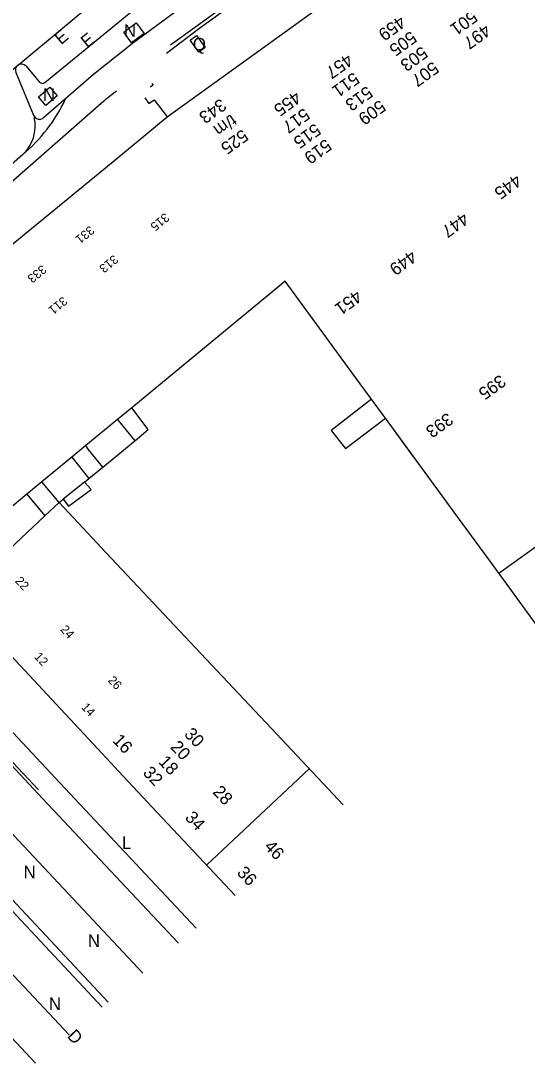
# Model space of a CAD drawing. Extents: x 81617 to 82144, y 454649 to 455150.
# Drawn here: x 81909.6 to 81949.9, y 454809.9 to 454892.9 of the extents above; entities that cross this region are included whole.
import ezdxf

# ---------------------------------------------------------------- set-up
doc = ezdxf.new("R2010")
doc.units = 0
doc.layers.add('B-WE-OG-TOPOGRAFIE-G', color=7, linetype='Continuous')
doc.layers.add('B-WE-VW-MARKERING-G', color=7, linetype='Continuous')

msp = doc.modelspace()

# ---------------------------------------------------------------- linework, layer by layer
at = {"layer": 'B-WE-OG-TOPOGRAFIE-G'}
for p, q in [((81950.918, 454911.808), (81923.86, 454892.262)), ((81944.326, 454907.373), (81921.528, 454890.929)), ((81923.86, 454892.262), (81921.201, 454890.255)), ((81909.22, 454888.733), (81910.638, 454885.336)), ((81917.237, 454887.263), (81916.786, 454886.922)), ((81916.221, 454886.463), (81896.497, 454869.183)), ((81919.488, 454886.723), (81919.813, 454886.277)), ((81919.813, 454886.277), (81920.236, 454886.581)), ((81920.236, 454886.581), (81921.268, 454885.205)), ((81937.511, 454862.758), (81934.312, 454860.275)), ((81937.511, 454862.758), (81934.312, 454860.275)), ((81937.511, 454862.758), (81934.312, 454860.275)), ((81918.444, 454862.075), (81917.306, 454861.136)), ((81917.306, 454861.136), (81914.799, 454859.068)), ((81917.306, 454861.136), (81918.676, 454859.457)), ((81935.433, 454858.848), (81938.614, 454861.25)), ((81935.433, 454858.848), (81938.614, 454861.25)), ((81935.433, 454858.848), (81938.614, 454861.25)), ((81934.312, 454860.275), (81935.433, 454858.848)), ((81934.312, 454860.275), (81935.433, 454858.848)), ((81934.312, 454860.275), (81935.433, 454858.848)), ((81914.799, 454859.068), (81913.685, 454858.149)), ((81916.149, 454857.354), (81918.676, 454859.457)), ((81913.685, 454858.149), (81911.291, 454856.174)), ((81913.685, 454858.149), (81915.028, 454856.444)), ((81915.028, 454856.444), (81916.149, 454857.354)), ((81914.671, 454856.155), (81915.028, 454856.444)), ((81911.291, 454856.174), (81910.108, 454855.198)), ((81912.663, 454854.533), (81911.291, 454856.174)), ((81914.671, 454856.155), (81912.984, 454854.792)), ((81910.108, 454855.198), (81905.083, 454851.053)), ((81910.108, 454855.198), (81911.539, 454853.481)), ((81912.663, 454854.533), (81912.984, 454854.792)), ((81947.643, 454848.911), (81956.042, 454855)), ((81911.539, 454853.481), (81912.663, 454854.533)), ((81906.763, 454849.012), (81911.539, 454853.481)), ((81924.393, 454825.698), (81932.567, 454833.351)), ((81906.018, 454826.058), (81916.564, 454814.799)), ((81916.1, 454814.409), (81905.567, 454825.643))]:
    msp.add_line(p, q, dxfattribs=at)
for points in [[(81917.092, 454881.782), (81921.268, 454885.205), (81949.801, 454905.786)], [(81919.999, 454898.128), (81906.308, 454886.765), (81902.426, 454883.614), (81900.642, 454882.153)], [(81911.534, 454887.943), (81921.736, 454896.324)], [(81911.427, 454885.151), (81915.4, 454888.603), (81918.504, 454891.084), (81923.337, 454894.66)], [(81919.423, 454891.854), (81918.433, 454891.108), (81917.801, 454891.947), (81918.791, 454892.693), (81919.423, 454891.854)], [(81923.597, 454891.675), (81924.274, 454890.72), (81923.769, 454890.369), (81923.093, 454891.323), (81923.597, 454891.675)], [(81910.021, 454889.265), (81911.115, 454887.981)], [(81920.043, 454887.868), (81920.135, 454887.739), (81919.902, 454887.577)], [(81911.027, 454886.805), (81911.932, 454887.574), (81912.512, 454886.885), (81911.605, 454886.11), (81911.027, 454886.805)], [(81891.095, 454859.963), (81890.844, 454860.269), (81917.092, 454881.782)], [(81951.285, 454843.934), (81946.864, 454849.976), (81944.717, 454852.907), (81938.617, 454861.252), (81938.467, 454861.458), (81936.615, 454863.983), (81930.646, 454872.141), (81929.047, 454870.822)], [(81929.231, 454870.974), (81918.444, 454862.075)], [(81929.231, 454870.974), (81929.047, 454870.822)], [(81940.891, 454858.141), (81938.617, 454861.252), (81938.467, 454861.458), (81936.615, 454863.983), (81935.739, 454865.18)], [(81940.891, 454858.141), (81938.617, 454861.252), (81938.467, 454861.458), (81936.615, 454863.983), (81935.739, 454865.18)], [(81918.676, 454859.457), (81919.752, 454860.352), (81918.444, 454862.075)], [(81916.149, 454857.354), (81914.976, 454858.774), (81914.799, 454859.068)], [(81912.984, 454854.792), (81913.418, 454854.239), (81915.212, 454855.566), (81914.671, 454856.155)], [(81912.663, 454854.533), (81916.411, 454850.545), (81923.933, 454842.539)], [(81912.733, 454832.236), (81908.633, 454836.613), (81900.431, 454845.439), (81899.742, 454846.157), (81896.321, 454849.804), (81892.737, 454853.657), (81891.454, 454852.381)], [(81891.454, 454852.381), (81907.325, 454835.276), (81911.365, 454830.977)], [(81915.707, 454834.971), (81906.614, 454844.709), (81904.504, 454846.96), (81905.266, 454847.61)], [(81923.933, 454842.539), (81928.656, 454837.512), (81929.128, 454837.011), (81935.259, 454830.486)], [(81926.662, 454823.272), (81920.473, 454829.89), (81917.383, 454833.177), (81917.088, 454833.492), (81915.707, 454834.971)], [(81923.564, 454820.673), (81912.733, 454832.236)], [(81911.365, 454830.977), (81922.158, 454819.493)], [(81919.317, 454817.11), (81908.659, 454828.488)], [(81903.018, 454823.298), (81913.463, 454812.197)], [(81910.78, 454809.946), (81900.471, 454820.954)]]:
    msp.add_lwpolyline(points, dxfattribs=at)
for centre, radius, start, end in [((81909.674, 454888.918), 0.491, 45.00271, 202.18039), ((81911.343, 454888.175), 0.3, 220.42207, 309.41325), ((81922.811, 454878.941), 10, 127.04711, 131.2203), ((81911.099, 454885.528), 0.5, 202.6584, 310.9901)]:
    msp.add_arc(centre, radius, start, end, dxfattribs=at)
at = {"layer": 'B-WE-VW-MARKERING-G'}
for p, q in [((81909.745, 454882.201), (81907.947, 454880.616)), ((81900.01, 454843.365), (81911.022, 454831.689))]:
    msp.add_line(p, q, dxfattribs=at)
for centre, radius, start, end in [((81901.454, 454892.168), 12.965, 309.75214, 334.77886), ((81907.761, 454884.451), 3, 311.399, 13.66646)]:
    msp.add_arc(centre, radius, start, end, dxfattribs=at)

# ---------------------------------------------------------------- texts
at = {"layer": 'B-WE-OG-TOPOGRAFIE-G'}
for s, height, rotation, p in [('459', 1, 215.80311, (81939.769, 454893.31)), ('501', 1, 215.80311, (81945.478, 454893.729)), ('E', 1, 40.44825, (81912.821, 454890.901)), ('497', 1, 215.80311, (81946.537, 454892.643)), ('E', 1, 39.08186, (81914.893, 454890.651)), ('505', 1, 215.80311, (81940.643, 454892.091)), ('503', 1, 215.80311, (81941.521, 454890.874)), ('457', 1, 215.80311, (81935.587, 454890.293)), ('507', 1, 215.80311, (81942.402, 454889.66)), ('511', 1, 215.80311, (81936.091, 454888.807)), ('455', 1, 215.80311, (81931.454, 454887.312)), ('513', 1, 215.80311, (81937.144, 454887.717)), ('343', 1, 215.80311, (81925.506, 454886.721)), ('509', 1, 215.80311, (81938.174, 454886.611)), ('t/m', 1, 215.80311, (81926.343, 454885.475)), ('517', 1, 215.80311, (81932.14, 454885.958)), ('515', 1, 215.80311, (81933.014, 454884.739)), ('525', 1, 215.80311, (81927.242, 454884.274)), ('519', 1, 215.80311, (81933.872, 454883.508)), ('445', 1, 215.97914, (81948.99, 454880.706)), ('315', 0.7, 219.3386, (81921.07, 454877.607)), ('447', 1, 215.97914, (81944.797, 454877.662)), ('331', 0.7, 219.3386, (81915.102, 454876.595)), ('313', 0.7, 219.3386, (81917.004, 454874.275)), ('449', 1, 215.97914, (81940.654, 454874.654)), ('333', 0.7, 219.3386, (81911.293, 454873.474)), ('451', 1, 215.97914, (81936.297, 454871.491)), ('311', 0.7, 219.3386, (81912.961, 454870.962)), ('395', 1, 215.8412, (81947.736, 454864.758)), ('393', 1, 215.8412, (81943.547, 454861.733)), ('22', 0.7, 313.08215, (81909.116, 454848.257)), ('24', 0.7, 313.04046, (81912.717, 454844.402)), ('12', 0.7, 313.04046, (81910.639, 454842.231)), ('26', 0.7, 313.04046, (81916.497, 454840.353)), ('14', 0.7, 313.04046, (81914.385, 454838.219)), ('30', 1, 313.12438, (81922.555, 454836.068)), ('16', 1, 313.23057, (81916.855, 454835.565)), ('20', 1, 313.12438, (81921.46, 454835.042)), ('18', 1, 313.12438, (81920.51, 454833.862)), ('32', 1, 313.12438, (81919.268, 454832.994)), ('28', 1, 313.23057, (81924.822, 454831.47)), ('34', 1, 313.23057, (81922.62, 454829.432)), ('46', 1, 313.23057, (81928.916, 454827.114)), ('36', 1, 313.23057, (81926.746, 454825.043)), ('D', 1, 313.20083, (81913.245, 454812.058))]:
    msp.add_text(s, height=height, rotation=rotation, dxfattribs=at).set_placement(p)
for s, p in [('N', (81917.811, 454891.579)), ('Q', (81923.301, 454890.503)), ('N', (81911.383, 454886.479)), ('L', (81917.664, 454826.988)), ('N', (81909.832, 454824.657)), ('N', (81914.946, 454819.194)), ('N', (81911.846, 454814.171))]:
    msp.add_text(s, height=1, dxfattribs=at).set_placement(p)

doc.saveas('drawing.dxf')
